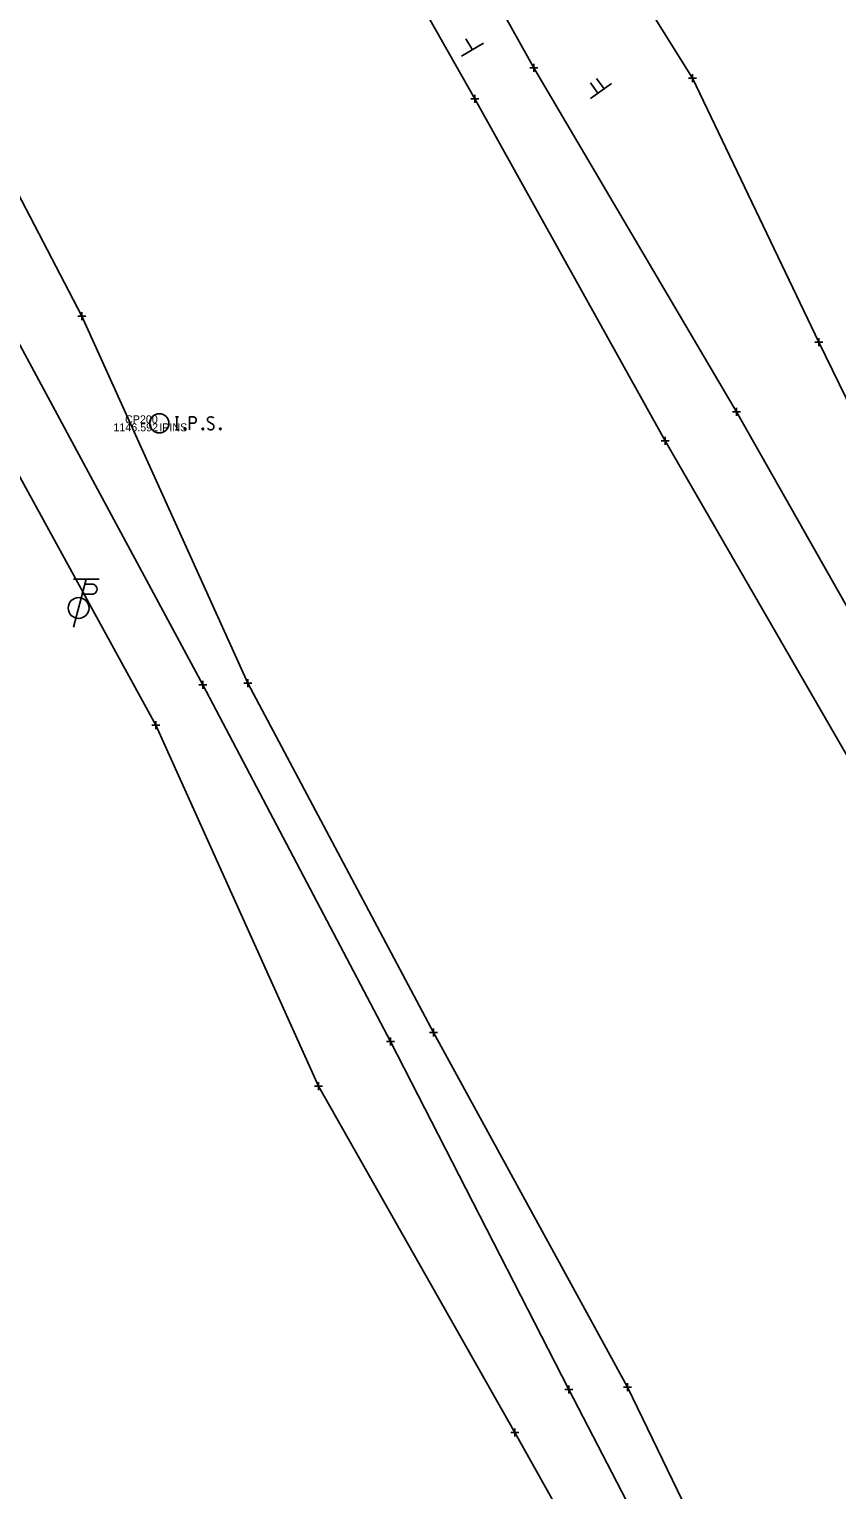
# Model space of a CAD drawing. Extents: x 2298098 to 2302860, y 557788 to 564251.
# Drawn here: x 2298830.2 to 2298931.1, y 562708 to 562890.5 of the extents above; entities that cross this region are included whole.
import ezdxf

# ---------------------------------------------------------------- set-up
doc = ezdxf.new("R2010")
doc.units = 0
for name, color, linetype in [('DR_X_Ditch', 7, 'Continuous'), ('RS_Raster1', 7, 'Continuous'), ('SN_X_Public', 7, 'Continuous'), ('SV_X_Break_Lines', 7, 'Continuous'), ('SV_X_Shot_Marker', 7, 'Continuous'), ('SV_X_Text_Comment', 7, 'Continuous'), ('SV_X_Text_Elevation', 7, 'Continuous'), ('SV_X_Text_Name', 7, 'Continuous'), ('UT_X_Misc_Cells', 7, 'Continuous')]:
    doc.layers.add(name, color=color, linetype=linetype)

msp = doc.modelspace()

# ---------------------------------------------------------------- linework, layer by layer
at = {"layer": 'DR_X_Ditch'}
for points in [[(2298990.32, 562712.48), (2298968.1, 562751.98), (2298943.57, 562798.51), (2298918.54, 562842.66), (2298893.21, 562885.66), (2298867.77, 562931.28), (2298845.25, 562972.8), (2298824.22, 563017.03), (2298800.1, 563060.77), (2298775.62, 563105.79)], [(2299003.75, 562520.37), (2298991.5, 562542.96), (2298967.32, 562586.85), (2298943.53, 562632.42), (2298920.95, 562675.39), (2298897.6, 562720.52), (2298875.32, 562763.99), (2298851.88, 562808.58), (2298829.06, 562850.95), (2298804.9, 562894.79), (2298774.65, 562954.26)]]:
    msp.add_lwpolyline(points, dxfattribs=at)
at = {"layer": 'RS_Raster1'}
for points in [[(2298848.46, 562842.04), (2298848.82, 562842.04)], [(2298848.46, 562842.04), (2298848.82, 562842.04)], [(2298848.64, 562840.44), (2298848.64, 562842.04)], [(2298848.64, 562840.44), (2298848.64, 562842.04)], [(2298850.2, 562840.44), (2298850.2, 562842.04), (2298850.73, 562842.04), (2298850.79, 562842.03), (2298850.87, 562842), (2298850.9, 562841.98), (2298850.93, 562841.95), (2298850.98, 562841.89), (2298851.01, 562841.83), (2298851.03, 562841.73), (2298851.03, 562841.57), (2298851.02, 562841.52), (2298851, 562841.45), (2298850.95, 562841.36), (2298850.91, 562841.32), (2298850.88, 562841.3), (2298850.82, 562841.27), (2298850.73, 562841.26), (2298850.2, 562841.26)], [(2298850.2, 562840.44), (2298850.2, 562842.04), (2298850.73, 562842.04), (2298850.79, 562842.03), (2298850.87, 562842), (2298850.9, 562841.98), (2298850.93, 562841.95), (2298850.98, 562841.89), (2298851.01, 562841.83), (2298851.03, 562841.73), (2298851.03, 562841.57), (2298851.02, 562841.52), (2298851, 562841.45), (2298850.95, 562841.36), (2298850.91, 562841.32), (2298850.88, 562841.3), (2298850.82, 562841.27), (2298850.73, 562841.26), (2298850.2, 562841.26)], [(2298853.21, 562841.93), (2298853.19, 562841.95), (2298853.16, 562841.98), (2298853.06, 562842.02), (2298852.94, 562842.04), (2298852.85, 562842.04), (2298852.82, 562842.04), (2298852.67, 562842), (2298852.55, 562841.93), (2298852.48, 562841.83), (2298852.45, 562841.73), (2298852.45, 562841.65), (2298852.48, 562841.55), (2298852.56, 562841.46), (2298853.17, 562841.08), (2298853.22, 562841.03), (2298853.25, 562840.98), (2298853.27, 562840.91), (2298853.27, 562840.83), (2298853.26, 562840.76), (2298853.25, 562840.71), (2298853.22, 562840.64), (2298853.2, 562840.59), (2298853.18, 562840.55), (2298853.15, 562840.52), (2298853.11, 562840.49), (2298853.07, 562840.47), (2298853.04, 562840.45), (2298852.94, 562840.44), (2298852.78, 562840.44), (2298852.68, 562840.47), (2298852.54, 562840.55), (2298852.45, 562840.63)], [(2298853.21, 562841.93), (2298853.19, 562841.95), (2298853.16, 562841.98), (2298853.06, 562842.02), (2298852.94, 562842.04), (2298852.85, 562842.04), (2298852.82, 562842.04), (2298852.67, 562842), (2298852.55, 562841.93), (2298852.48, 562841.83), (2298852.45, 562841.73), (2298852.45, 562841.65), (2298852.48, 562841.55), (2298852.56, 562841.46), (2298853.17, 562841.08), (2298853.22, 562841.03), (2298853.25, 562840.98), (2298853.27, 562840.91), (2298853.27, 562840.83), (2298853.26, 562840.76), (2298853.25, 562840.71), (2298853.22, 562840.64), (2298853.2, 562840.59), (2298853.18, 562840.55), (2298853.15, 562840.52), (2298853.11, 562840.49), (2298853.07, 562840.47), (2298853.04, 562840.45), (2298852.94, 562840.44), (2298852.78, 562840.44), (2298852.68, 562840.47), (2298852.54, 562840.55), (2298852.45, 562840.63)], [(2298848.46, 562840.44), (2298848.82, 562840.44)], [(2298848.46, 562840.44), (2298848.82, 562840.44)], [(2298849.6, 562840.65), (2298849.65, 562840.65), (2298849.69, 562840.63), (2298849.72, 562840.58), (2298849.72, 562840.52), (2298849.69, 562840.47), (2298849.65, 562840.44), (2298849.6, 562840.44), (2298849.57, 562840.47), (2298849.53, 562840.52), (2298849.53, 562840.58), (2298849.57, 562840.63), (2298849.6, 562840.65)], [(2298849.6, 562840.65), (2298849.65, 562840.65), (2298849.69, 562840.63), (2298849.72, 562840.58), (2298849.72, 562840.52), (2298849.69, 562840.47), (2298849.65, 562840.44), (2298849.6, 562840.44), (2298849.57, 562840.47), (2298849.53, 562840.52), (2298849.53, 562840.58), (2298849.57, 562840.63), (2298849.6, 562840.65)], [(2298851.85, 562840.65), (2298851.9, 562840.65), (2298851.94, 562840.63), (2298851.97, 562840.58), (2298851.97, 562840.52), (2298851.94, 562840.47), (2298851.9, 562840.44), (2298851.85, 562840.44), (2298851.81, 562840.47), (2298851.78, 562840.52), (2298851.78, 562840.58), (2298851.81, 562840.63), (2298851.85, 562840.65)], [(2298851.85, 562840.65), (2298851.9, 562840.65), (2298851.94, 562840.63), (2298851.97, 562840.58), (2298851.97, 562840.52), (2298851.94, 562840.47), (2298851.9, 562840.44), (2298851.85, 562840.44), (2298851.81, 562840.47), (2298851.78, 562840.52), (2298851.78, 562840.58), (2298851.81, 562840.63), (2298851.85, 562840.65)], [(2298854.03, 562840.65), (2298854.08, 562840.65), (2298854.12, 562840.63), (2298854.15, 562840.58), (2298854.15, 562840.52), (2298854.12, 562840.47), (2298854.08, 562840.44), (2298854.03, 562840.44), (2298854, 562840.47), (2298853.96, 562840.52), (2298853.96, 562840.58), (2298854, 562840.63), (2298854.03, 562840.65)], [(2298854.03, 562840.65), (2298854.08, 562840.65), (2298854.12, 562840.63), (2298854.15, 562840.58), (2298854.15, 562840.52), (2298854.12, 562840.47), (2298854.08, 562840.44), (2298854.03, 562840.44), (2298854, 562840.47), (2298853.96, 562840.52), (2298853.96, 562840.58), (2298854, 562840.63), (2298854.03, 562840.65)]]:
    msp.add_lwpolyline(points, dxfattribs=at)
msp.add_circle((2298846.44, 562841.24), 1.2, dxfattribs=at)
msp.add_circle((2298846.44, 562841.24), 1.2, dxfattribs=at)
at = {"layer": 'SN_X_Public'}
for p, q in [((2298885.57, 562887.93), (2298884.74, 562889.3)), ((2298886.94, 562888.75), (2298884.2, 562887.11)), ((2298901.22, 562882.48), (2298900.29, 562883.78)), ((2298902.91, 562883.69), (2298900.31, 562881.82)), ((2298902, 562883.04), (2298901.07, 562884.34)), ((2298901.61, 562882.76), (2298901.61, 562882.76))]:
    msp.add_line(p, q, dxfattribs=at)
at = {"layer": 'SV_X_Break_Lines'}
for points in [[(2299012.23, 562719.09), (2298995.81, 562724.81), (2298975.48, 562758.16), (2298952.6, 562802.63), (2298928.82, 562851.37), (2298913.06, 562884.39), (2298881.3, 562935.17), (2298854.82, 562982.31), (2298842.18, 563007.84), (2298815.07, 563063.43), (2298795.4, 563105.82), (2298773.55, 563154.81), (2298750.4, 563200.04), (2298726.9, 563240.12), (2298697.59, 563291.08), (2298669.52, 563329.34), (2298635.82, 563380.83)], [(2298987.22, 562709.11), (2298959.25, 562753), (2298935.67, 562794), (2298909.63, 562839.05), (2298885.86, 562881.77), (2298861.27, 562925.14), (2298837.45, 562968.46), (2298815.16, 563012.33), (2298793.19, 563055.34), (2298768.49, 563101.46)], [(2298776.72, 562954.86), (2298790.71, 562942.29), (2298813.67, 562899.02), (2298836.78, 562854.64), (2298857.48, 562808.76), (2298880.71, 562765.1), (2298904.94, 562720.81), (2298926.21, 562676.8), (2298949.69, 562632.19), (2298970.3, 562586.72), (2298995.59, 562544.53), (2299008.11, 562519.62)], [(2299001.55, 562517.92), (2298988, 562540.14), (2298965.59, 562585.47), (2298938.68, 562626.84), (2298915.47, 562671.2), (2298890.85, 562715.15), (2298866.34, 562758.43), (2298846.01, 562803.54), (2298821.84, 562847.56), (2298795.62, 562890.45), (2298777.34, 562936.82), (2298773.04, 562953.6)]]:
    msp.add_lwpolyline(points, dxfattribs=at)
at = {"layer": 'SV_X_Shot_Marker'}
for p, q in [((2298892.71, 562885.66), (2298893.71, 562885.66)), ((2298893.21, 562886.16), (2298893.21, 562885.16)), ((2298893.21, 562885.66), (2298893.21, 562885.66)), ((2298912.56, 562884.39), (2298913.56, 562884.39)), ((2298913.06, 562884.89), (2298913.06, 562883.89)), ((2298913.06, 562884.39), (2298913.06, 562884.39)), ((2298885.36, 562881.77), (2298886.36, 562881.77)), ((2298885.86, 562882.27), (2298885.86, 562881.27)), ((2298885.86, 562881.77), (2298885.86, 562881.77)), ((2298836.28, 562854.64), (2298837.28, 562854.64)), ((2298836.78, 562855.14), (2298836.78, 562854.14)), ((2298836.78, 562854.64), (2298836.78, 562854.64)), ((2298928.32, 562851.37), (2298929.32, 562851.37)), ((2298928.82, 562851.87), (2298928.82, 562850.87)), ((2298928.82, 562851.37), (2298928.82, 562851.37)), ((2298918.54, 562843.16), (2298918.54, 562842.16)), ((2298918.04, 562842.66), (2298919.04, 562842.66)), ((2298918.54, 562842.66), (2298918.54, 562842.66)), ((2298909.63, 562839.55), (2298909.63, 562838.55)), ((2298909.13, 562839.05), (2298910.13, 562839.05)), ((2298909.63, 562839.05), (2298909.63, 562839.05)), ((2298851.38, 562808.58), (2298852.38, 562808.58)), ((2298851.88, 562809.08), (2298851.88, 562808.08)), ((2298851.88, 562808.58), (2298851.88, 562808.58)), ((2298856.98, 562808.76), (2298857.98, 562808.76)), ((2298857.48, 562809.26), (2298857.48, 562808.26)), ((2298857.48, 562808.76), (2298857.48, 562808.76)), ((2298845.51, 562803.54), (2298846.51, 562803.54)), ((2298846.01, 562804.04), (2298846.01, 562803.04)), ((2298846.01, 562803.54), (2298846.01, 562803.54)), ((2298880.21, 562765.1), (2298881.21, 562765.1)), ((2298880.71, 562765.6), (2298880.71, 562764.6)), ((2298880.71, 562765.1), (2298880.71, 562765.1)), ((2298874.82, 562763.99), (2298875.82, 562763.99)), ((2298875.32, 562764.49), (2298875.32, 562763.49)), ((2298875.32, 562763.99), (2298875.32, 562763.99)), ((2298865.84, 562758.43), (2298866.84, 562758.43)), ((2298866.34, 562758.93), (2298866.34, 562757.93)), ((2298866.34, 562758.43), (2298866.34, 562758.43)), ((2298897.6, 562721.02), (2298897.6, 562720.02)), ((2298904.94, 562721.31), (2298904.94, 562720.31)), ((2298897.1, 562720.52), (2298898.1, 562720.52)), ((2298897.6, 562720.52), (2298897.6, 562720.52)), ((2298904.44, 562720.81), (2298905.44, 562720.81)), ((2298904.94, 562720.81), (2298904.94, 562720.81)), ((2298890.85, 562715.65), (2298890.85, 562714.65)), ((2298890.35, 562715.15), (2298891.35, 562715.15)), ((2298890.85, 562715.15), (2298890.85, 562715.15))]:
    msp.add_line(p, q, dxfattribs=at)
at = {"layer": 'UT_X_Misc_Cells'}
for p, q in [((2298837.32, 562821.76), (2298835.71, 562815.76)), ((2298838.92, 562821.76), (2298835.72, 562821.76)), ((2298836.82, 562819.88), (2298838.01, 562819.88)), ((2298837.16, 562821.16), (2298838.01, 562821.16))]:
    msp.add_line(p, q, dxfattribs=at)
msp.add_circle((2298836.36, 562818.16), 1.3, dxfattribs=at)
msp.add_arc((2298838.02, 562820.52), 0.638, 268.8767, 91.1233, dxfattribs=at)

# ---------------------------------------------------------------- texts
at = {"layer": 'SV_X_Text_Comment'}
msp.add_text('IPINS', height=1, dxfattribs=at).set_placement((2298846.44, 562840.24))
at = {"layer": 'SV_X_Text_Elevation'}
msp.add_text('1146.592', height=1, dxfattribs=at).set_placement((2298840.71, 562840.24))
at = {"layer": 'SV_X_Text_Name'}
msp.add_text('CP200', height=1, dxfattribs=at).set_placement((2298842.16, 562841.24))

doc.saveas('drawing.dxf')
